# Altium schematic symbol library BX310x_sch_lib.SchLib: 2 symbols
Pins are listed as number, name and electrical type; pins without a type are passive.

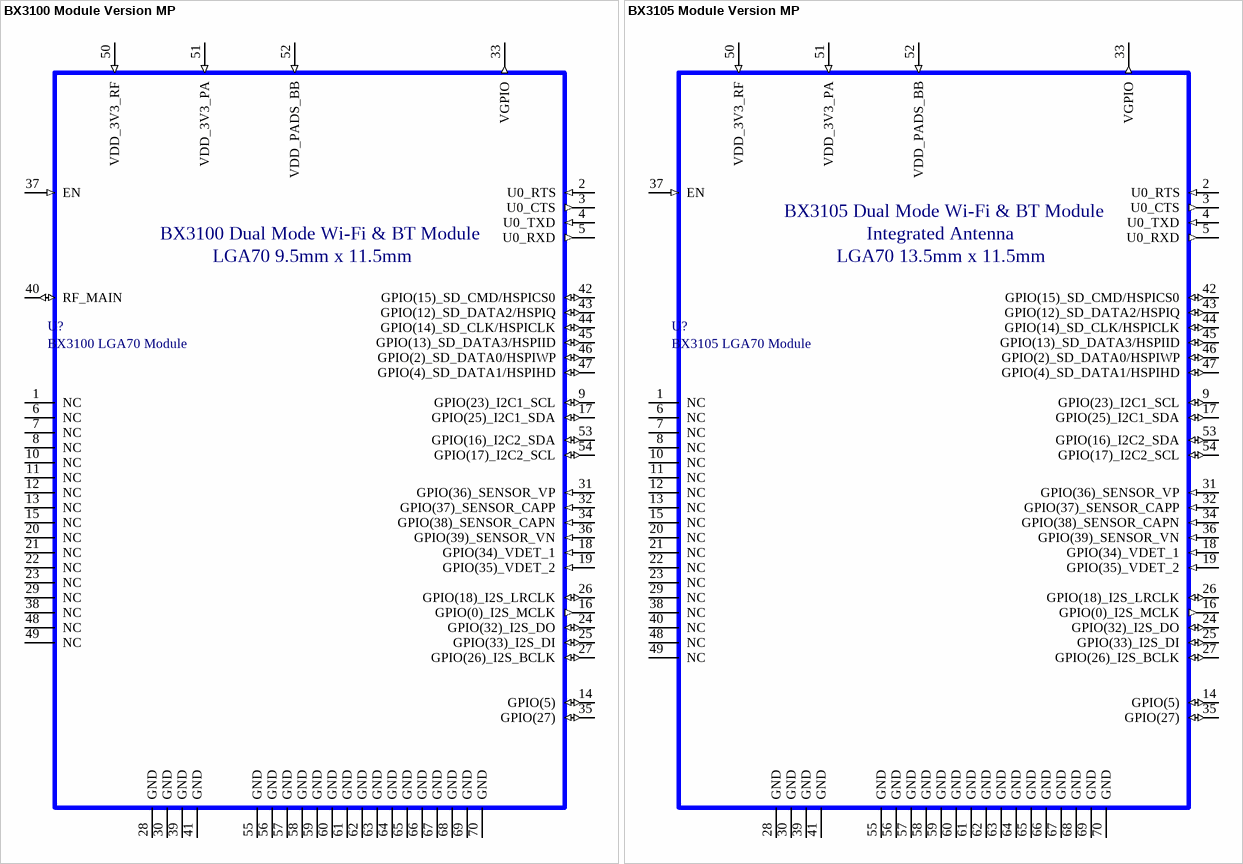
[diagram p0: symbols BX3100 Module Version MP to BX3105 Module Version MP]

## BX3100 Module Version MP
designator U?, comment BX3100 LGA70 Module
BX3100 Module Version MP; Manufacturer: Sierra Wireless
footprint LGA70 BX3100 MP (LGA, 70-Leads, Body 9.5x11.5mm, Pitch 0.65mm)
pins: 1 NC (hiz), 2 U0_RTS (in), 3 U0_CTS (out), 4 U0_TXD (in), 5 U0_RXD (out), 6 NC (hiz), 7 NC (hiz), 8 NC (hiz), 9 GPIO(23)_I2C1_SCL (io), 10 NC (hiz), 11 NC (hiz), 12 NC (hiz), 13 NC (hiz), 14 GPIO(5) (io), 15 NC (hiz), 16 GPIO(0)_I2S_MCLK (out), 17 GPIO(25)_I2C1_SDA (io), 18 GPIO(34)_VDET_1 (in), 19 GPIO(35)_VDET_2 (in), 20 NC (hiz), 21 NC (hiz), 22 NC (hiz), 23 NC (hiz), 24 GPIO(32)_I2S_DO (io), 25 GPIO(33)_I2S_DI (io), 26 GPIO(18)_I2S_LRCLK (io), 27 GPIO(26)_I2S_BCLK (io), 28 GND (power), 29 NC (hiz), 30 GND (power), 31 GPIO(36)_SENSOR_VP (in), 32 GPIO(37)_SENSOR_CAPP (in), 33 VGPIO (out), 34 GPIO(38)_SENSOR_CAPN (in), 35 GPIO(27) (io), 36 GPIO(39)_SENSOR_VN (in), 37 EN (in), 38 NC (hiz), 39 GND (power), 40 RF_MAIN (io), 41 GND (power), 42 GPIO(15)_SD_CMD/HSPICS0 (io), 43 GPIO(12)_SD_DATA2/HSPIQ (io), 44 GPIO(14)_SD_CLK/HSPICLK (io), 45 GPIO(13)_SD_DATA3/HSPIID (io), 46 GPIO(2)_SD_DATA0/HSPIWP (io), 47 GPIO(4)_SD_DATA1/HSPIHD (io), 48 NC (hiz), 49 NC (hiz), 50 VDD_3V3_RF (in), 51 VDD_3V3_PA (in), 52 VDD_PADS_BB (in), 53 GPIO(16)_I2C2_SDA (io), 54 GPIO(17)_I2C2_SCL (io), 55 GND (power), 56 GND (power), 57 GND (power), 58 GND (power), 59 GND (power), 60 GND (power), 61 GND (power), 62 GND (power), 63 GND (power), 64 GND (power), 65 GND (power), 66 GND (power), 67 GND (power), 68 GND (power), 69 GND (power), 70 GND (power)

## BX3105 Module Version MP
designator U?, comment BX3105 LGA70 Module
BX3105 Module Version MP; Manufacturer: Sierra Wireless
footprint LGA70 BX3105 MP (LGA, 70-Leads, Body 13.5x11.5mm, Pitch 0.65mm)
pins: 1 NC (hiz), 2 U0_RTS (in), 3 U0_CTS (out), 4 U0_TXD (in), 5 U0_RXD (out), 6 NC (hiz), 7 NC (hiz), 8 NC (hiz), 9 GPIO(23)_I2C1_SCL (io), 10 NC (hiz), 11 NC (hiz), 12 NC (hiz), 13 NC (hiz), 14 GPIO(5) (io), 15 NC (hiz), 16 GPIO(0)_I2S_MCLK (out), 17 GPIO(25)_I2C1_SDA (io), 18 GPIO(34)_VDET_1 (in), 19 GPIO(35)_VDET_2 (in), 20 NC (hiz), 21 NC (hiz), 22 NC (hiz), 23 NC (hiz), 24 GPIO(32)_I2S_DO (io), 25 GPIO(33)_I2S_DI (io), 26 GPIO(18)_I2S_LRCLK (io), 27 GPIO(26)_I2S_BCLK (io), 28 GND (power), 29 NC (hiz), 30 GND (power), 31 GPIO(36)_SENSOR_VP (in), 32 GPIO(37)_SENSOR_CAPP (in), 33 VGPIO (out), 34 GPIO(38)_SENSOR_CAPN (in), 35 GPIO(27) (io), 36 GPIO(39)_SENSOR_VN (in), 37 EN (in), 38 NC (hiz), 39 GND (power), 40 NC (hiz), 41 GND (power), 42 GPIO(15)_SD_CMD/HSPICS0 (io), 43 GPIO(12)_SD_DATA2/HSPIQ (io), 44 GPIO(14)_SD_CLK/HSPICLK (io), 45 GPIO(13)_SD_DATA3/HSPIID (io), 46 GPIO(2)_SD_DATA0/HSPIWP (io), 47 GPIO(4)_SD_DATA1/HSPIHD (io), 48 NC (hiz), 49 NC (hiz), 50 VDD_3V3_RF (in), 51 VDD_3V3_PA (in), 52 VDD_PADS_BB (in), 53 GPIO(16)_I2C2_SDA (io), 54 GPIO(17)_I2C2_SCL (io), 55 GND (power), 56 GND (power), 57 GND (power), 58 GND (power), 59 GND (power), 60 GND (power), 61 GND (power), 62 GND (power), 63 GND (power), 64 GND (power), 65 GND (power), 66 GND (power), 67 GND (power), 68 GND (power), 69 GND (power), 70 GND (power)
